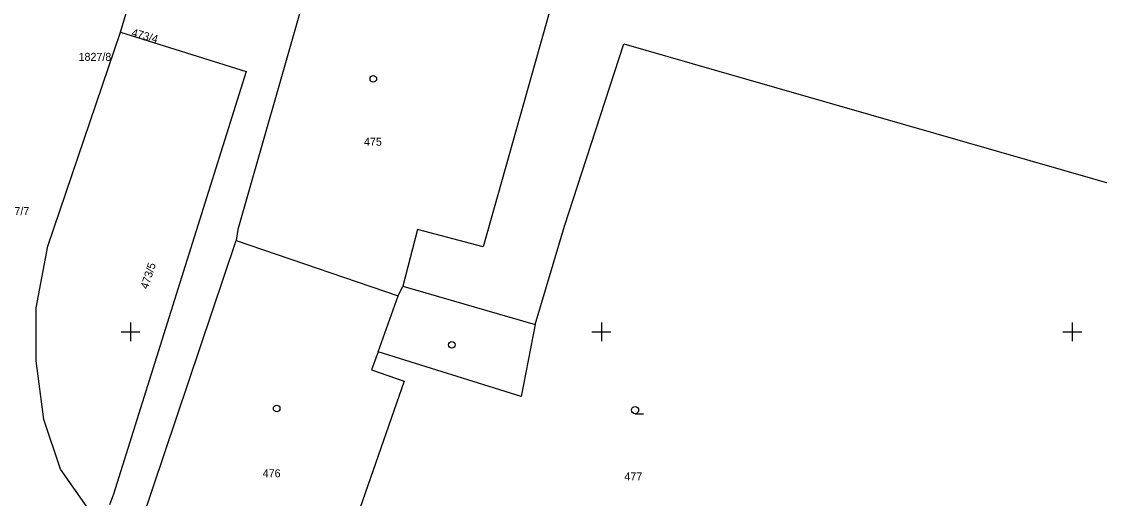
# Model space of a CAD drawing. Extents: x -702257 to -701487, y -1009871 to -1008841.
# Drawn here: x -701730.8 to -701673.6, y -1008958.9 to -1008933.5 of the extents above; entities that cross this region are included whole.
import ezdxf

# ---------------------------------------------------------------- set-up
doc = ezdxf.new("R2010")
doc.units = 0
for name, color, linetype in [('Z_hektometricka_sit', 7, 'Continuous'), ('Z_katastr_cisla_pozemkova', 7, 'Continuous'), ('Z_katastr_cisla_stavebni', 7, 'Continuous'), ('Z_katastr_hranice', 7, 'Continuous'), ('Z_katastr_vnitrni_kresba', 7, 'Continuous'), ('Z_katastr_znacky_budov', 7, 'Continuous'), ('Z_katastr_znacky_kultur', 7, 'Continuous')]:
    doc.layers.add(name, color=color, linetype=linetype)

msp = doc.modelspace()

# ---------------------------------------------------------------- linework, layer by layer
at = {"layer": 'Z_hektometricka_sit'}
for p, q in [((-701725, -1008949.5), (-701725, -1008950.5)), ((-701725, -1008949.5), (-701725, -1008950.5)), ((-701700, -1008949.5), (-701700, -1008950.5)), ((-701700, -1008949.5), (-701700, -1008950.5)), ((-701675, -1008949.5), (-701675, -1008950.5)), ((-701675, -1008949.5), (-701675, -1008950.5)), ((-701725.5, -1008950), (-701724.5, -1008950)), ((-701725.5, -1008950), (-701724.5, -1008950)), ((-701700.5, -1008950), (-701699.5, -1008950)), ((-701700.5, -1008950), (-701699.5, -1008950)), ((-701675.5, -1008950), (-701674.5, -1008950)), ((-701675.5, -1008950), (-701674.5, -1008950))]:
    msp.add_line(p, q, dxfattribs=at)
at = {"layer": 'Z_katastr_hranice'}
for p, q in [((-701714.52, -1008927.78), (-701719.29, -1008944.57)), ((-701725.53, -1008934.07), (-701724.37, -1008930.24)), ((-701729.38, -1008945.45), (-701725.53, -1008934.07)), ((-701725.53, -1008934.07), (-701718.86, -1008936.17)), ((-701700.79, -1008940.79), (-701698.81, -1008934.7)), ((-701698.81, -1008934.7), (-701694.02, -1008936.08)), ((-701718.86, -1008936.17), (-701725.9, -1008958.63)), ((-701694.02, -1008936.08), (-701671.27, -1008942.62)), ((-701701.96, -1008944.39), (-701700.79, -1008940.79)), ((-701703.52, -1008949.61), (-701701.96, -1008944.39)), ((-701719.29, -1008944.57), (-701719.39, -1008945.14)), ((-701730.01, -1008948.72), (-701729.38, -1008945.45)), ((-701724.46, -1008960.21), (-701719.39, -1008945.14)), ((-701719.39, -1008945.14), (-701710.78, -1008948.09)), ((-701710.78, -1008948.09), (-701710.54, -1008947.57)), ((-701710.54, -1008947.57), (-701703.52, -1008949.61)), ((-701730.01, -1008951.55), (-701730.01, -1008948.72)), ((-701703.52, -1008949.61), (-701704.26, -1008953.43)), ((-701711.85, -1008951.06), (-701712.2, -1008952.02)), ((-701704.26, -1008953.43), (-701711.85, -1008951.06)), ((-701729.59, -1008954.65), (-701730.01, -1008951.55)), ((-701712.2, -1008952.02), (-701710.46, -1008952.63)), ((-701710.46, -1008952.63), (-701715.75, -1008967.79)), ((-701728.71, -1008957.3), (-701729.59, -1008954.65)), ((-701726.55, -1008960.38), (-701728.71, -1008957.3)), ((-701725.9, -1008958.63), (-701726.11, -1008959.2))]:
    msp.add_line(p, q, dxfattribs=at)
at = {"layer": 'Z_katastr_vnitrni_kresba'}
for p, q in [((-701702.26, -1008931.22), (-701706.28, -1008945.49)), ((-701709.76, -1008944.57), (-701710.54, -1008947.57)), ((-701706.28, -1008945.49), (-701709.76, -1008944.57)), ((-701711.85, -1008951.06), (-701710.78, -1008948.09))]:
    msp.add_line(p, q, dxfattribs=at)
at = {"layer": 'Z_katastr_znacky_budov'}
for centre in [(-701712.107, -1008936.559), (-701707.937, -1008950.689), (-701717.237, -1008954.079)]:
    msp.add_circle(centre, 0.175, dxfattribs=at)
at = {"layer": 'Z_katastr_znacky_kultur'}
msp.add_line((-701698.208, -1008954.35), (-701697.771, -1008954.35), dxfattribs=at)
msp.add_circle((-701698.208, -1008954.162), 0.187, dxfattribs=at)

# ---------------------------------------------------------------- texts
at = {"layer": 'Z_katastr_cisla_pozemkova'}
for s, rotation, p in [('473/4', 344, (-701724.974, -1008934.277)), ('473/5', 72, (-701724.081, -1008947.762))]:
    msp.add_text(s, height=0.425, rotation=rotation, dxfattribs=at).set_placement(p)
for s, p in [('1827/8', (-701727.754, -1008935.6)), ('1827/7', (-701732.109, -1008943.799)), ('477', (-701698.779, -1008957.9))]:
    msp.add_text(s, height=0.425, dxfattribs=at).set_placement(p)
at = {"layer": 'Z_katastr_cisla_stavebni'}
for s, p in [('475', (-701712.603, -1008940.11)), ('476', (-701717.979, -1008957.73))]:
    msp.add_text(s, height=0.425, dxfattribs=at).set_placement(p)

doc.saveas('drawing.dxf')
